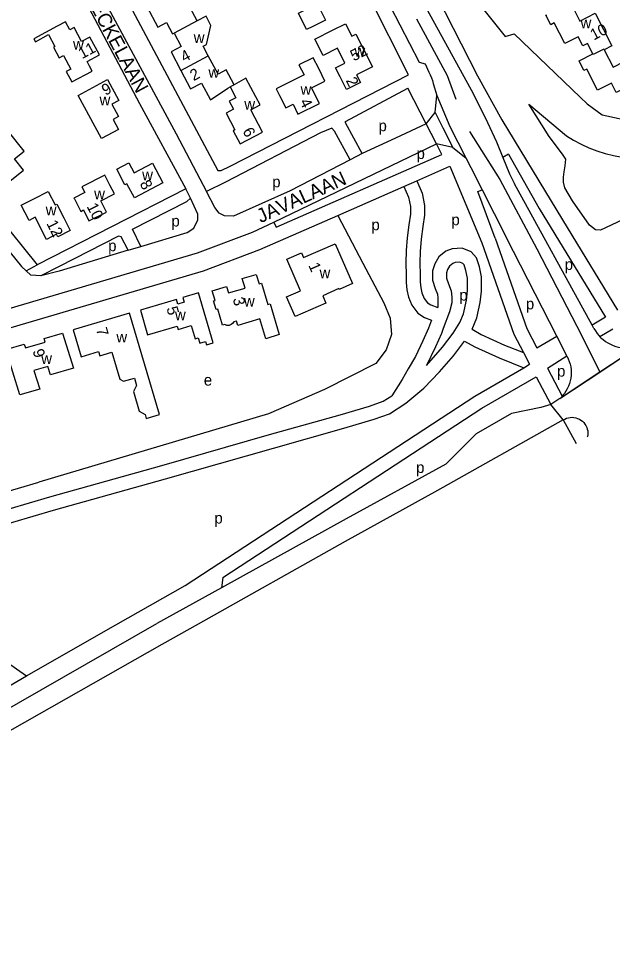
# Model space of a CAD drawing. Extents: x 162427 to 165104, y 384242 to 386287.
# Drawn here: x 163508.3 to 163720.2, y 384515.8 to 384850.5 of the extents above; entities that cross this region are included whole.
import ezdxf

# ---------------------------------------------------------------- set-up
doc = ezdxf.new("R2010")
doc.units = 0
for name, color, linetype in [('BLT_Basislijn', 7, 'Continuous'), ('BLT_Bebouwing', 7, 'Continuous'), ('BLT_Centroide', 7, 'Continuous'), ('BLT_Huisnummer', 7, 'Continuous'), ('BLT_Huisnummer_ tussenligend', 7, 'Continuous'), ('BLT_Huisnummer_reeks', 7, 'Continuous'), ('BLT_Onderverdeling_panden', 7, 'Continuous'), ('BLT_Straatnaam', 7, 'Continuous'), ('BLT_Vlakafsluiter', 7, 'Continuous')]:
    doc.layers.add(name, color=color, linetype=linetype)

msp = doc.modelspace()

# ---------------------------------------------------------------- linework, layer by layer
at = {"layer": 'BLT_Basislijn'}
for p, q in [((163417.99, 384883.24), (163514.84, 384762.64)), ((163647.49, 384830.54), (163621.68, 384881.66)), ((163653.79, 384813.03), (163647.28, 384825.73)), ((163656.95, 384817.08), (163657.57, 384823.12)), ((163656.95, 384817.08), (163659.73, 384811.62)), ((163697.65, 384808.52), (163690.42, 384820)), ((163690.42, 384820), (163703.89, 384808.7)), ((163653.79, 384813.03), (163642.8, 384807.92)), ((163642.8, 384807.92), (163630.91, 384802.38)), ((163657.49, 384805.85), (163655.6, 384809.52)), ((163702.48, 384802.15), (163697.65, 384808.52)), ((163663.29, 384804.61), (163667.9, 384800.84)), ((163630.91, 384802.38), (163626.63, 384800.11)), ((163683.11, 384802.21), (163681.15, 384801)), ((163703.63, 384800.42), (163702.48, 384802.15)), ((163703.39, 384797.96), (163703.63, 384800.42)), ((163662.21, 384797.87), (163673.68, 384770.54)), ((163669.76, 384797.37), (163673.81, 384789.38)), ((163703, 384795.86), (163703.39, 384797.96)), ((163768.27, 384799.98), (163715.99, 384775.02)), ((163702.77, 384792.13), (163702.85, 384793.92)), ((163702.85, 384793.92), (163703, 384795.86)), ((163712.98, 384741.11), (163685.26, 384791.58)), ((163703.32, 384790.11), (163702.77, 384792.13)), ((163567.94, 384789.85), (163514.84, 384762.64)), ((163569.66, 384786.51), (163567.94, 384789.85)), ((163673.81, 384789.38), (163682.32, 384772.59)), ((163706.04, 384785.52), (163703.32, 384790.11)), ((163712.03, 384776.81), (163706.04, 384785.52)), ((163704.09, 384775.97), (163722.07, 384746.45)), ((163714.2, 384775.18), (163712.03, 384776.81)), ((163715.99, 384775.02), (163714.2, 384775.18)), ((163700.42, 384737.16), (163682.32, 384772.59)), ((163547.39, 384767.92), (163551.86, 384769.23)), ((163511.01, 384760.54), (163514.84, 384762.64)), ((163717.75, 384743.92), (163712.98, 384741.11)), ((163713.64, 384739.92), (163712.98, 384741.11)), ((163693.27, 384733.03), (163700.42, 384737.16)), ((163704, 384730.15), (163700.42, 384737.16)), ((163720.36, 384739.65), (163715.82, 384736.99)), ((163697.07, 384725.76), (163704, 384730.15)), ((163704.09, 384729.98), (163704, 384730.15)), ((163688.59, 384725.92), (163690.7, 384727.15)), ((163671.12, 384715.77), (163688.59, 384725.92)), ((163697.07, 384725.76), (163702.3, 384715.73)), ((163673.63, 384711.45), (163693.02, 384722.71)), ((163693.02, 384722.71), (163698.22, 384712.74)), ((163701.47, 384714.89), (163698.22, 384712.74)), ((163701.47, 384714.89), (163701.85, 384715.14)), ((163701.94, 384715.26), (163701.85, 384715.14)), ((163702.3, 384715.73), (163701.94, 384715.26)), ((163581.23, 384651.03), (163673.63, 384711.45)), ((163698.22, 384712.74), (163694.69, 384711.71)), ((163597.44, 384709.5), (163515.54, 384685.05)), ((163702.7, 384707.25), (163707.36, 384698.83)), ((163581.23, 384651.03), (163580.69, 384647.31)), ((163580.69, 384647.31), (163557.56, 384634.54)), ((163511.09, 384615.84), (163542.94, 384634.07)), ((163559.35, 384627.11), (163500, 384593.4)), ((163503.13, 384621.48), (163511.09, 384615.84)), ((163351.72, 384524.66), (163511.09, 384615.84))]:
    msp.add_line(p, q, dxfattribs=at)
for points in [[(163499.13, 384918.85), (163551.47, 384820.31), (163567.94, 384789.85)], [(163515.79, 384908.62), (163518.62, 384909.99), (163519.44, 384908.92), (163579.41, 384796.34), (163580.59, 384796.32), (163583.77, 384797.88), (163647.49, 384830.54)], [(163512.07, 384906.8), (163564.56, 384809.44), (163575.38, 384788.87)], [(163412.77, 384881.27), (163509.26, 384762.09), (163511.01, 384760.54)], [(163627.15, 384881.85), (163651.3, 384835.03), (163653.38, 384834.46), (163654.73, 384831.46)], [(163648.85, 384875.79), (163672.15, 384830.12), (163680.83, 384814.45)], [(163655.02, 384875.1), (163656.82, 384875.74), (163682.02, 384844.18), (163685.23, 384845.12), (163708.81, 384822.49), (163711.21, 384820.11), (163716.64, 384816.24), (163722.73, 384814.86), (163729.83, 384814.83), (163734.58, 384814.89), (163739.86, 384815.36), (163744.65, 384816.02), (163749.74, 384817.26), (163754.17, 384818.73), (163759.07, 384821.05), (163780.9, 384832.02)], [(163647.62, 384865.79), (163670.55, 384823.88), (163675.64, 384813.5), (163678.85, 384806.52), (163681.15, 384801)], [(163650.36, 384850.51), (163661.3, 384830.31), (163664.32, 384821.81)], [(163654.73, 384831.46), (163655.23, 384830.49), (163655.67, 384829.48), (163656.03, 384828.44), (163656.31, 384827.38), (163657.57, 384823.12)], [(163630.91, 384802.38), (163625.01, 384813.31), (163625.01, 384813.79), (163647.28, 384825.73)], [(163680.83, 384814.45), (163698.37, 384785.35), (163704.09, 384775.97)], [(163626.63, 384800.11), (163621, 384810.44), (163620.14, 384811.49), (163616.1, 384809.75), (163582.16, 384792.14), (163575.38, 384788.87)], [(163669.3, 384810.25), (163680.05, 384793.07), (163693.25, 384768.35), (163707.58, 384740.79), (163715.76, 384724.42)], [(163703.89, 384808.7), (163706.43, 384807.13), (163709.09, 384805.7), (163711.86, 384804.42), (163714.73, 384803.32), (163717.69, 384802.39), (163720.7, 384801.64), (163723.77, 384801.09), (163726.86, 384800.73), (163729.96, 384800.58), (163733.06, 384800.61), (163736.13, 384800.85), (163739.15, 384801.27), (163742.11, 384801.87), (163745, 384802.64)], [(163599.37, 384777.91), (163600.2, 384776.11), (163659.4, 384802.1), (163657.49, 384805.85)], [(163599.37, 384777.91), (163657.49, 384805.85)], [(163667.9, 384800.84), (163669.71, 384797.46), (163669.76, 384797.37)], [(163681.15, 384801), (163683.57, 384795.2), (163685.26, 384791.58)], [(163683.11, 384802.21), (163694.06, 384782.82), (163717.75, 384743.92)], [(163626.63, 384800.11), (163605.18, 384789.04), (163584.93, 384780.06), (163581.73, 384780.1), (163579.89, 384781.08), (163578.3, 384783.15), (163575.38, 384788.87)], [(163650.39, 384792.69), (163662.21, 384797.87)], [(163622.19, 384780.3), (163645.82, 384790.68)], [(163645.82, 384790.68), (163650.39, 384792.69)], [(163645.82, 384790.68), (163647.49, 384786.81), (163648.14, 384783.43), (163648.14, 384780.7), (163647.6, 384776.96), (163647.04, 384772.26), (163646.66, 384767.73), (163646.47, 384763.32), (163646.66, 384759.01), (163646.66, 384756.38), (163646.87, 384753.67), (163647.51, 384751.1), (163648.61, 384748.22), (163650.78, 384745.34), (163653.22, 384743.87), (163655.67, 384742.89)], [(163650.39, 384792.69), (163652.3, 384788.29), (163653.14, 384783.9), (163653.14, 384780.34), (163652.56, 384776.31), (163652.01, 384771.76), (163651.65, 384767.41), (163651.47, 384763.32), (163651.66, 384759.12), (163651.66, 384756.57), (163651.82, 384754.47), (163652.28, 384752.6), (163653.03, 384750.67), (163654.19, 384749.12), (163655.45, 384748.36), (163657.93, 384747.37)], [(163678.4, 384772.19), (163672.2, 384788.82), (163673.81, 384789.38)], [(163551.86, 384769.23), (163548.87, 384775.39), (163568.28, 384785.22), (163569.66, 384786.51)], [(163551.86, 384769.23), (163568.43, 384774.23), (163570.82, 384775.77), (163572.25, 384778.73), (163572.25, 384780.78), (163569.66, 384786.51)], [(163472.81, 384730.65), (163574.26, 384760.53), (163594.34, 384768.08), (163622.19, 384780.3)], [(163622.19, 384780.3), (163631.2, 384763.22), (163638.63, 384749.14), (163640.88, 384743.6), (163641.37, 384737.72), (163639.49, 384732.3), (163635.84, 384727.44), (163617.48, 384718.18), (163597.44, 384709.5)], [(163472.81, 384730.65), (163473.82, 384735.65), (163475.22, 384737.73), (163477.45, 384738.99), (163572.13, 384766.88), (163591.82, 384774.28), (163599.37, 384777.91)], [(163547.39, 384767.92), (163544.89, 384772.7), (163543.94, 384772.87), (163522.75, 384762.09), (163516.16, 384758.78)], [(163673.68, 384770.54), (163685.08, 384737.92), (163688.52, 384731.32)], [(163678.4, 384772.19), (163689.68, 384739.91), (163693.27, 384733.03)], [(163547.39, 384767.92), (163522.78, 384760.37), (163516.16, 384758.78)], [(163670.18, 384739.63), (163671.89, 384743.7), (163673.08, 384749.24), (163673.47, 384753.21), (163673.47, 384758.36), (163672.84, 384761.93), (163671.69, 384765.15), (163669.89, 384767.24), (163666.58, 384768.63), (163663.04, 384768.38), (163660.85, 384767.55), (163658.34, 384765.54), (163656.83, 384763.04), (163656.08, 384760.54), (163656.08, 384757.23), (163656.96, 384754.17), (163657.8, 384752.16), (163657.93, 384750.8), (163657.93, 384747.37)], [(163653.9, 384726.69), (163659.59, 384733.26), (163663.37, 384738.29), (163665.79, 384742.1), (163667.1, 384745.2), (163668.13, 384750.02), (163668.47, 384753.45), (163668.47, 384757.92), (163667.99, 384760.64), (163667.29, 384762.6), (163666.87, 384763.09), (163665.75, 384763.56), (163664.12, 384763.44), (163663.35, 384763.15), (163662.16, 384762.2), (163661.44, 384761.01), (163661.08, 384759.81), (163661.08, 384757.93), (163661.69, 384755.82), (163662.7, 384753.39), (163662.93, 384751.05), (163662.93, 384749.11)], [(163516.16, 384758.78), (163512.66, 384759), (163511.01, 384760.54)], [(163662.93, 384749.11), (163662.11, 384745.88), (163659.9, 384739.93)], [(163655.67, 384742.89), (163654.6, 384740.03), (163652.62, 384735.51), (163649.91, 384729.91), (163647.36, 384725.54), (163645.16, 384721.69), (163641.52, 384715.93)], [(163659.9, 384739.93), (163659.24, 384738.15), (163657.16, 384733.42), (163653.9, 384726.69)], [(163670.18, 384739.63), (163673.4, 384737.8), (163681.75, 384733.99), (163688.52, 384731.32)], [(163713.64, 384739.92), (163714.17, 384739.03), (163714.77, 384738.18), (163715.43, 384737.39), (163715.82, 384736.99)], [(163715.82, 384736.99), (163716.15, 384736.64), (163716.93, 384735.96), (163717.76, 384735.33), (163718.63, 384734.78), (163719.55, 384734.29), (163720.49, 384733.87), (163721.47, 384733.53), (163722.47, 384733.27), (163723.49, 384733.08), (163724.42, 384732.98)], [(163624.39, 384704.33), (163635.16, 384707.49), (163640.65, 384709.45), (163646.57, 384713.21), (163652.9, 384718.58), (163658.58, 384724.45), (163663.49, 384730.12), (163667.46, 384735.42)], [(163667.46, 384735.42), (163671.13, 384733.34), (163679.79, 384729.39), (163688.59, 384725.92)], [(163688.52, 384731.32), (163690.7, 384727.15)], [(163704.09, 384729.98), (163704.52, 384729.08), (163704.88, 384728.15), (163705.16, 384727.19), (163705.37, 384726.21), (163705.49, 384725.21), (163705.54, 384724.21), (163705.51, 384723.21), (163705.39, 384722.22), (163705.2, 384721.24), (163704.93, 384720.27), (163704.58, 384719.33), (163704.16, 384718.42), (163703.67, 384717.55), (163703.11, 384716.72), (163702.49, 384715.94), (163702.3, 384715.73)], [(163715.76, 384724.42), (163715.79, 384724.38)], [(163567.68, 384648.16), (163671.12, 384715.77)], [(163623.03, 384709.14), (163633.58, 384712.24), (163638.44, 384713.97), (163641.52, 384715.93)], [(163694.69, 384711.71), (163684.22, 384709.62), (163671.66, 384702.29), (163660.84, 384691.46), (163625.25, 384671.91), (163580.69, 384647.31)], [(163471.2, 384678.31), (163475.64, 384673.05), (163477.7, 384671.67), (163481.2, 384670.38), (163484.32, 384670.2), (163487.08, 384670.48), (163490.22, 384671.29), (163519.39, 384679.86), (163559.36, 384691.05), (163597.88, 384702.02), (163623.03, 384709.14)], [(163702.7, 384707.25), (163657.84, 384682.11), (163624.8, 384663.81)], [(163702.7, 384707.25), (163703.28, 384707.59), (163703.9, 384707.86), (163704.54, 384708.05), (163705.2, 384708.17), (163705.87, 384708.2), (163706.55, 384708.16), (163707.21, 384708.04), (163707.85, 384707.84), (163708.46, 384707.56), (163709.04, 384707.21), (163709.57, 384706.8), (163710.04, 384706.33), (163710.46, 384705.8), (163710.82, 384705.23), (163711.1, 384704.62), (163711.31, 384703.98), (163711.44, 384703.33), (163711.49, 384702.66), (163711.46, 384701.98), (163711.35, 384701.32), (163711.28, 384701.08)], [(163467.43, 384673.97), (163475.42, 384667.18), (163480.17, 384665.43), (163484.43, 384665.18), (163487.96, 384665.55), (163491.55, 384666.47), (163520.77, 384675.06), (163560.72, 384686.24), (163599.24, 384697.21), (163624.39, 384704.33)], [(163465.99, 384684.23), (163486.36, 384676.44), (163515.54, 384685.05)], [(163624.8, 384663.81), (163572.4, 384634.38), (163559.35, 384627.11)], [(163542.94, 384634.07), (163567.68, 384648.16)], [(163350, 384515.76), (163466.83, 384582.52), (163557.56, 384634.54)]]:
    msp.add_lwpolyline(points, dxfattribs=at)
at = {"layer": 'BLT_Bebouwing'}
for points in [[(163617.44, 384864.01), (163621.2, 384856.51), (163615.87, 384853.84), (163617.8, 384849.99), (163613.32, 384847.76), (163611.09, 384846.64), (163608.17, 384852.49), (163610.77, 384853.79), (163608.02, 384859.3), (163609.31, 384859.95)], [(163572.02, 384849.74), (163568.6, 384856.19), (163566.71, 384855.19), (163564.06, 384860.19), (163563.61, 384859.95)], [(163554.1, 384854.91), (163558.02, 384847.51), (163561.1, 384849.15), (163563.25, 384845.09), (163563.82, 384845.4)], [(163705.32, 384856.29), (163708.69, 384849.7), (163714.13, 384852.48), (163720.08, 384840.86), (163717.32, 384839.44)], [(163576, 384837.27), (163574.19, 384840.68), (163575.35, 384841.29), (163576.95, 384848.06), (163575.17, 384851.41), (163572.02, 384849.74)], [(163713.27, 384837.99), (163711.37, 384841.7), (163709.68, 384840.84), (163708.01, 384844.1), (163703.26, 384841.67), (163699.49, 384849.03), (163698.27, 384848.4), (163696.54, 384851.79), (163696.81, 384851.93)], [(163526.91, 384832.53), (163525.25, 384831.64), (163527.24, 384827.95), (163534.52, 384831.87), (163533.58, 384833.63), (163532.69, 384835.29), (163537.1, 384837.65), (163533.7, 384843.98), (163530.74, 384842.39), (163528.07, 384847.35), (163526.54, 384846.53), (163524.97, 384849.46), (163522.09, 384847.92), (163513.68, 384843.4), (163514.25, 384842.34), (163518.94, 384844.86), (163521.22, 384840.6), (163520.76, 384840.36), (163522.79, 384836.56), (163524.31, 384837.38), (163526.91, 384832.53)], [(163628.94, 384830.52), (163630.31, 384827.82), (163625.31, 384825.29), (163623.05, 384829.75), (163621.4, 384833.03), (163624.75, 384834.72), (163622.1, 384839.97), (163616.94, 384837.36), (163613.98, 384843.21), (163620.52, 384846.52), (163624.99, 384848.77), (163627.25, 384844.29), (163628.69, 384845.02), (163634.58, 384833.37), (163628.94, 384830.52)], [(163563.82, 384845.4), (163566.36, 384840.61), (163562.68, 384838.66), (163566.18, 384832.07)], [(163585.23, 384826.97), (163582.4, 384832.3), (163579.47, 384830.74), (163576, 384837.27)], [(163732.59, 384829.7), (163732.95, 384829.01), (163725.12, 384825), (163724.71, 384825.78), (163721.62, 384824.2), (163719.91, 384827.55), (163714.98, 384825.02), (163711.13, 384832.52), (163710.12, 384832), (163708.35, 384835.47), (163713.27, 384837.99)], [(163717.32, 384839.44), (163720.53, 384833.19), (163728.68, 384837.37), (163729.17, 384836.42)], [(163615.4, 384832.72), (163613.44, 384836.63), (163608.35, 384834.07), (163610.16, 384830.46), (163600.2, 384825.46), (163601.37, 384823.13), (163603.62, 384818.66), (163606.23, 384819.97), (163608.01, 384816.42), (163615.67, 384820.27), (163612.87, 384825.86), (163617.65, 384828.26), (163615.4, 384832.72)], [(163566.18, 384832.07), (163569.68, 384825.48), (163573.59, 384827.55), (163576.75, 384821.59), (163583.02, 384825.75), (163583.8, 384826.18)], [(163542, 384814.51), (163543.9, 384810.99), (163537.83, 384807.72), (163529.48, 384823.16), (163540.06, 384828.86), (163544.09, 384821.37), (163541.59, 384820.02), (163543.98, 384815.58), (163542, 384814.51)], [(163583.8, 384826.18), (163585.85, 384822.3), (163583.49, 384821.06), (163585.01, 384818.2), (163582.34, 384816.78), (163585.46, 384810.89), (163584.85, 384810.56), (163587.36, 384805.82), (163595.36, 384810.07), (163591.14, 384818.02), (163594.48, 384819.79), (163592.98, 384822.61), (163589.43, 384829.31), (163585.23, 384826.97)], [(163499.83, 384804.42), (163500, 384804.2), (163502.16, 384801.5), (163500, 384799.78), (163496.88, 384797.29), (163500, 384793.38), (163502.38, 384790.4), (163506.29, 384793.52), (163509.98, 384796.47), (163506.78, 384800.49), (163510.21, 384803.22), (163504.62, 384810.23), (163502.8, 384808.77), (163499.99, 384806.54), (163499.74, 384806.34), (163498.86, 384805.63), (163499.83, 384804.42)], [(163543.29, 384796.77), (163547.65, 384799.08), (163549.54, 384795.52), (163556.08, 384798.99), (163559.81, 384791.96), (163549.64, 384786.57), (163546.95, 384791.63), (163546.22, 384791.24), (163543.29, 384796.77)], [(163542.45, 384787.97), (163540.86, 384791.1), (163539.05, 384794.67), (163530.86, 384790.52), (163531.91, 384788.46), (163528.02, 384786.49), (163528.17, 384786.2), (163530.43, 384781.74), (163531.43, 384782.24), (163533.39, 384778.37), (163539.61, 384781.52), (163537.59, 384785.51), (163542.45, 384787.97)], [(163524.39, 384779.38), (163526.65, 384774.92), (163522.24, 384772.68), (163521.8, 384773.56), (163518.19, 384771.73), (163514.19, 384779.62), (163511.98, 384778.5), (163509.21, 384783.96), (163513.67, 384786.22), (163518.87, 384788.85), (163521.3, 384784.06), (163521.87, 384784.35), (163524.39, 384779.38)], [(163627.46, 384755.95), (163622.74, 384753.88), (163622.61, 384754.17), (163616.86, 384751.64), (163618.01, 384749.02), (163607.02, 384744.2), (163603.94, 384751.23), (163608.91, 384753.41), (163603.97, 384764.65), (163609.23, 384766.96), (163609.98, 384765.25), (163621.28, 384770.21), (163627.46, 384755.95)], [(163597.23, 384748.49), (163598.09, 384748.71), (163601.29, 384737.72), (163596.55, 384736.28), (163594.39, 384743.4), (163586.49, 384741), (163586.01, 384742.57), (163585.06, 384742.28), (163584.65, 384741.7), (163584.13, 384741.3), (163583.39, 384741.04), (163582.61, 384741.05), (163581.88, 384741.31), (163581.1, 384741.08), (163579.35, 384746.84), (163578.83, 384746.68), (163577.9, 384749.74), (163578.41, 384749.9), (163577.36, 384753.36), (163582.48, 384754.91), (163583.16, 384752.62), (163589.14, 384754.37), (163588.12, 384757.82), (163593.12, 384759.25), (163594.13, 384755.84), (163594.99, 384756.08), (163597.23, 384748.49)], [(163537.25, 384730.14), (163541.55, 384731.41), (163543.08, 384726.19), (163544.36, 384721.82), (163545.76, 384721.06), (163549.6, 384722.2), (163550.38, 384719.55), (163549.23, 384717.44), (163551.32, 384710.37), (163553.43, 384709.23), (163553.85, 384707.81), (163558.58, 384709.21), (163547.89, 384745.38), (163527.75, 384739.41), (163530.59, 384729.81), (163536.81, 384731.65), (163537.25, 384730.14)], [(163510.74, 384733.01), (163517.77, 384735.01), (163517.37, 384736.39), (163523.88, 384738.3), (163527.82, 384725.74), (163519.62, 384723.4), (163518.7, 384726.33), (163513.74, 384724.92), (163515.83, 384718.24), (163508.76, 384716.23), (163503.72, 384732.39), (163510.26, 384734.3), (163510.74, 384733.01)]]:
    msp.add_lwpolyline(points, dxfattribs=at)
msp.add_lwpolyline([(163551.74, 384746.51), (163554.34, 384737.65), (163564.88, 384740.75), (163565.22, 384739.58), (163569.88, 384740.94), (163571.25, 384736.26), (163572.41, 384736.6), (163572.98, 384734.69), (163574.95, 384735.27), (163575.29, 384734.12), (163577.75, 384734.78), (163572.52, 384752.61), (163566.93, 384750.98), (163567.41, 384749.34), (163565.1, 384748.65), (163564.6, 384750.31)], close=True, dxfattribs=at)
at = {"layer": 'BLT_Onderverdeling_panden'}
for p, q in [((163572.02, 384849.74), (163563.82, 384845.4)), ((163566.18, 384832.07), (163576, 384837.27)), ((163585.23, 384826.97), (163583.8, 384826.18))]:
    msp.add_line(p, q, dxfattribs=at)
msp.add_lwpolyline([(163717.32, 384839.44), (163717.2, 384839.69), (163713.4, 384837.74), (163713.27, 384837.99)], dxfattribs=at)
at = {"layer": 'BLT_Vlakafsluiter'}
for p, q in [((163653.79, 384813.03), (163656.95, 384817.08)), ((163655.6, 384809.52), (163653.79, 384813.03)), ((163659.73, 384811.62), (163663.29, 384804.61)), ((163663.29, 384804.61), (163657.49, 384805.85)), ((163715.76, 384724.42), (163729.52, 384733.54)), ((163715.79, 384724.38), (163729.66, 384733.58)), ((163701.85, 384715.14), (163715.79, 384724.38)), ((163701.94, 384715.26), (163715.76, 384724.42)), ((163702.7, 384707.25), (163698.22, 384712.74))]:
    msp.add_line(p, q, dxfattribs=at)
msp.add_lwpolyline([(163657.57, 384823.12), (163662.18, 384812.02), (163667.9, 384800.84)], dxfattribs=at)

# ---------------------------------------------------------------- texts
at = {"layer": 'BLT_Centroide'}
for s, p in [('w', (163708.88, 384847.12)), ('w', (163570.78, 384841.84)), ('w', (163527.7, 384839.47)), ('w', (163628.15, 384837.03)), ('w', (163576.02, 384829.44)), ('w', (163608.92, 384823.36)), ('w', (163537.16, 384819.61)), ('w', (163588.84, 384818.06)), ('p', (163636.76, 384810.37)), ('p', (163650.33, 384800.44)), ('w', (163552.36, 384792.81)), ('p', (163598.81, 384790.34)), ('w', (163535.23, 384786.03)), ('w', (163517.94, 384780.31)), ('p', (163562.83, 384776.34)), ('p', (163634.23, 384774.99)), ('p', (163662.8, 384776.8)), ('p', (163540.24, 384767.52)), ('p', (163703.24, 384760.84)), ('w', (163615.7, 384757.88)), ('w', (163588.71, 384747.75)), ('p', (163665.6, 384749.89)), ('p', (163689.37, 384746.75)), ('w', (163564.09, 384742.88)), ('w', (163543.17, 384734.94)), ('w', (163516.33, 384727.25)), ('p', (163700.5, 384722.73)), ('e', (163574.39, 384719.54)), ('p', (163650.19, 384688.32)), ('p', (163578.18, 384670.27))]:
    msp.add_text(s, height=4, dxfattribs=at).set_placement(p)
at = {"layer": 'BLT_Huisnummer'}
for s, rotation, p in [('10', 27.1284, (163713.6, 384842.73)), ('11', 28.2114, (163530.91, 384836.06)), ('2', 27.9491, (163570.75, 384828.21)), ('9', 28.2977, (163539.25, 384822.98)), ('4', 296.6624, (163608.5, 384820.89)), ('6', 297.9512, (163588.11, 384810.44)), ('8', 297.9383, (163551.39, 384791.67)), ('10', 296.8899, (163532.46, 384783.55)), ('12', 296.872, (163518.1, 384777.46)), ('1', 293.701, (163611.64, 384762.47)), ('3', 284.5396, (163584.69, 384750.54)), ('5', 286.3652, (163561.01, 384747.17)), ('7', 286.3617, (163535.83, 384739.62)), ('9', 286.4887, (163513.21, 384731.97))]:
    msp.add_text(s, height=4, rotation=rotation, dxfattribs=at).set_placement(p)
at = {"layer": 'BLT_Huisnummer_ tussenligend'}
msp.add_text('4', height=4, rotation=27.9491, dxfattribs=at).set_placement((163567.42, 384834.86))
at = {"layer": 'BLT_Huisnummer_reeks'}
for s, rotation, p in [('52', 26.8167, (163627.93, 384835.26)), ('2', 296.8059, (163624.97, 384828.5))]:
    msp.add_text(s, height=4, rotation=rotation, dxfattribs=at).set_placement(p)
at = {"layer": 'BLT_Straatnaam'}
for s, rotation, p in [('THORBECKELAAN', 298.1101, (163522.61, 384875.63)), ('JAVALAAN', 24.5316, (163594.68, 384777.48))]:
    msp.add_text(s, height=5, rotation=rotation, dxfattribs=at).set_placement(p)

doc.saveas('drawing.dxf')
